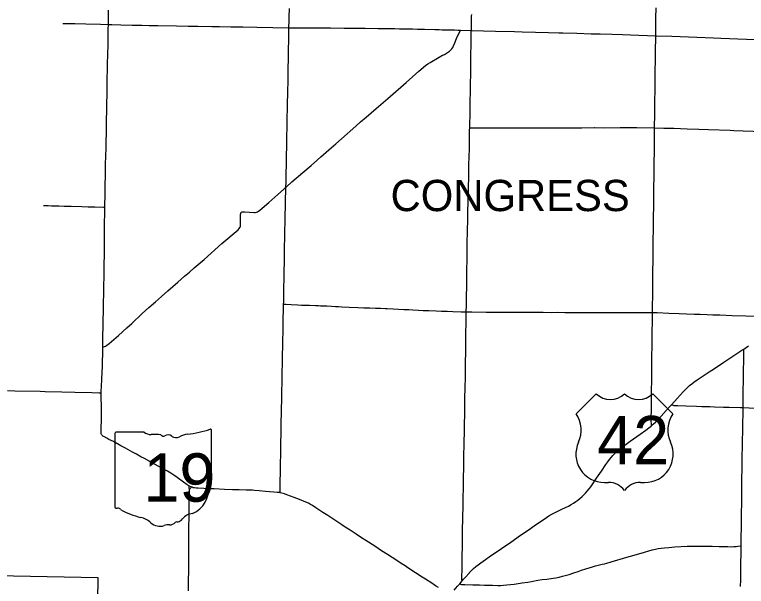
# Model space of a CAD drawing. Extents: x 9078 to 9739, y 4248 to 4966.
# Drawn here: x 9460 to 9565.4, y 4699.7 to 4782 of the extents above; entities that cross this region are included whole.
import ezdxf

# ---------------------------------------------------------------- set-up
doc = ezdxf.new("R2010")
doc.units = 0
for name, color, linetype in [('GM_X_County_Road', 7, 'Continuous'), ('GM_X_State_Route', 7, 'Continuous'), ('GM_X_State_Shield', 7, 'Continuous'), ('GM_X_Township', 7, 'Continuous'), ('GM_X_Township_Road', 7, 'Continuous'), ('GM_X_Township_Text', 7, 'Continuous'), ('GM_X_US_Route', 7, 'Continuous'), ('GM_X_US_Shield', 7, 'Continuous')]:
    doc.layers.add(name, color=color, linetype=linetype)

msp = doc.modelspace()

# ---------------------------------------------------------------- linework, layer by layer
at = {"layer": 'GM_X_County_Road'}
for points in [[(9499.49, 4780.1), (9499.49, 4780.17), (9499.5, 4780.99), (9499.51, 4781.64), (9499.54, 4782.87)], [(9525.74, 4779.71), (9525.75, 4779.86), (9525.76, 4780.44), (9525.77, 4781.34), (9525.79, 4781.75), (9525.82, 4781.99)], [(9499.05, 4757.13), (9499.07, 4757.84), (9499.07, 4758.17), (9499.09, 4758.82), (9499.09, 4759.4), (9499.11, 4760.13), (9499.13, 4760.95), (9499.14, 4761.53), (9499.14, 4761.85), (9499.15, 4762.18), (9499.16, 4762.51), (9499.17, 4763), (9499.19, 4763.66), (9499.2, 4764.56), (9499.23, 4765.62), (9499.25, 4766.35), (9499.25, 4766.74), (9499.25, 4766.98), (9499.25, 4767.3), (9499.25, 4767.54), (9499.26, 4768.03), (9499.26, 4768.61), (9499.28, 4769.18), (9499.29, 4769.67), (9499.3, 4770.17), (9499.32, 4770.9), (9499.34, 4771.47), (9499.35, 4771.88), (9499.37, 4772.79), (9499.38, 4773.44), (9499.39, 4773.85), (9499.39, 4774.59), (9499.4, 4775.25), (9499.42, 4776.31), (9499.44, 4777.05), (9499.45, 4778.2), (9499.49, 4780.1)], [(9499.05, 4757.13), (9499.12, 4757.2), (9499.92, 4757.9), (9501.47, 4759.24), (9502.66, 4760.25), (9503.59, 4761.06), (9504.08, 4761.49), (9505.24, 4762.52), (9506.23, 4763.39), (9507.03, 4764.1), (9509.11, 4765.94), (9509.79, 4766.54), (9510.59, 4767.24), (9512.02, 4768.48), (9513.7, 4769.92), (9516.36, 4772.23), (9518.21, 4773.85), (9519.16, 4774.64), (9519.49, 4774.89), (9519.83, 4775.11), (9521.11, 4775.85), (9521.61, 4776.12), (9521.89, 4776.26), (9522.31, 4776.51), (9522.58, 4776.7), (9522.76, 4776.87), (9522.92, 4777.06), (9523.06, 4777.26), (9523.18, 4777.47), (9523.37, 4777.92), (9523.61, 4778.53), (9523.8, 4778.98), (9524.02, 4779.43), (9524.14, 4779.64), (9524.2, 4779.75)], [(9499.49, 4780.1), (9499.74, 4780.1), (9500.31, 4780.09), (9501.95, 4780.09), (9504.33, 4780.07), (9505.47, 4780.06), (9507.44, 4780.04), (9508.59, 4780.04), (9510.48, 4780.02), (9512.28, 4780), (9513.18, 4779.99), (9514.74, 4779.96), (9515.39, 4779.95), (9515.64, 4779.94), (9516.13, 4779.94), (9517.28, 4779.92), (9518.01, 4779.9), (9518.42, 4779.89), (9518.99, 4779.88), (9520.47, 4779.84), (9521.12, 4779.82), (9521.53, 4779.81), (9523.01, 4779.78), (9523.33, 4779.77), (9523.82, 4779.76), (9524.2, 4779.75)], [(9524.2, 4779.75), (9525.74, 4779.71)], [(9525.51, 4765.67), (9525.53, 4766.09), (9525.56, 4767.65), (9525.58, 4768.47), (9525.58, 4769.12), (9525.59, 4769.61), (9525.62, 4770.76), (9525.63, 4771.66), (9525.66, 4773.8), (9525.69, 4775.02), (9525.69, 4776.01), (9525.71, 4777.81), (9525.73, 4778.88), (9525.74, 4779.71)], [(9525.74, 4779.71), (9525.87, 4779.7), (9527.51, 4779.67), (9529.23, 4779.61), (9531.94, 4779.53), (9533.08, 4779.49), (9534.97, 4779.44), (9536.85, 4779.39), (9538.33, 4779.35), (9538.9, 4779.35), (9540.95, 4779.29), (9543, 4779.22), (9544.31, 4779.2), (9546.03, 4779.15), (9547.5, 4779.11), (9548.65, 4779.08), (9552.31, 4778.95)], [(9552.14, 4765.7), (9552.14, 4766.16), (9552.15, 4767.23), (9552.15, 4767.72), (9552.17, 4768.62), (9552.18, 4769.36), (9552.18, 4770.02), (9552.2, 4770.67), (9552.21, 4771.66), (9552.22, 4772.56), (9552.24, 4774.12), (9552.25, 4775.1), (9552.26, 4775.76), (9552.28, 4776.83), (9552.31, 4778.71), (9552.31, 4778.8), (9552.31, 4778.95)], [(9552.31, 4778.95), (9552.42, 4778.95), (9554.63, 4778.87), (9560.61, 4778.63), (9561.68, 4778.59), (9565.37, 4778.46), (9567.09, 4778.4), (9567.99, 4778.38), (9569.38, 4778.33), (9571.27, 4778.27), (9573.89, 4778.19), (9576.92, 4778.09), (9577.91, 4778.06), (9578.2, 4778.04), (9578.33, 4778.02), (9578.46, 4777.99)], [(9525.02, 4739.17), (9525.02, 4739.28), (9525.03, 4740.02), (9525.05, 4741.17), (9525.08, 4743.13), (9525.09, 4744.2), (9525.12, 4745.51), (9525.13, 4746.41), (9525.15, 4748.05), (9525.15, 4748.55), (9525.16, 4749.53), (9525.18, 4750.35), (9525.2, 4751.33), (9525.22, 4751.99), (9525.23, 4752.65), (9525.26, 4753.79), (9525.28, 4754.86), (9525.3, 4755.68), (9525.33, 4756.58), (9525.35, 4757.32), (9525.37, 4758.38), (9525.39, 4759.53), (9525.41, 4760.35), (9525.47, 4762.65), (9525.48, 4763.55), (9525.5, 4765.11), (9525.5, 4765.35), (9525.51, 4765.67)], [(9551.83, 4739.08), (9551.83, 4739.66), (9551.86, 4741.88), (9551.88, 4744.01), (9551.89, 4745.08), (9551.91, 4746.47), (9551.92, 4747.21), (9551.92, 4748.03), (9551.93, 4748.77), (9551.95, 4749.75), (9551.96, 4750.82), (9551.98, 4751.97), (9552, 4753.12), (9552.02, 4754.1), (9552.03, 4755), (9552.03, 4755.66), (9552.04, 4756.48), (9552.05, 4757.38), (9552.07, 4758.37), (9552.07, 4759.44), (9552.09, 4760.99), (9552.1, 4761.98), (9552.1, 4762.39), (9552.11, 4763.04), (9552.13, 4764.6), (9552.14, 4765.59), (9552.14, 4765.7)], [(9492.62, 4753.5), (9492.67, 4753.54), (9492.74, 4753.57), (9492.82, 4753.58), (9493.07, 4753.58), (9493.81, 4753.52), (9494.47, 4753.5), (9494.63, 4753.51), (9494.79, 4753.54), (9494.95, 4753.59), (9495.09, 4753.67), (9495.29, 4753.81), (9496.59, 4754.95), (9497.89, 4756.09), (9498.68, 4756.8), (9499.05, 4757.13)], [(9498.71, 4740.29), (9498.73, 4740.63), (9498.75, 4741.53), (9498.75, 4741.94), (9498.76, 4742.76), (9498.79, 4743.91), (9498.81, 4745.22), (9498.82, 4746.13), (9498.84, 4746.7), (9498.85, 4747.44), (9498.85, 4748.26), (9498.85, 4748.58), (9498.89, 4749.73), (9498.91, 4750.88), (9498.93, 4752.03), (9498.94, 4752.6), (9498.95, 4753.01), (9498.96, 4753.42), (9498.97, 4753.99), (9498.98, 4754.56), (9498.99, 4754.89), (9499, 4755.63), (9499.03, 4756.37), (9499.05, 4756.94), (9499.05, 4757.13)], [(9472.68, 4734.1), (9472.93, 4734.2), (9473.09, 4734.26), (9473.23, 4734.34), (9473.61, 4734.65), (9474.92, 4735.78), (9476.14, 4736.87), (9476.87, 4737.53), (9478.37, 4738.94), (9479.33, 4739.83), (9480.26, 4740.64), (9481.12, 4741.4), (9482.05, 4742.21), (9483.47, 4743.45), (9484.46, 4744.32), (9485.14, 4744.91), (9485.82, 4745.5), (9487.26, 4746.73), (9489.84, 4749.01), (9492.15, 4751), (9492.32, 4751.17), (9492.41, 4751.31), (9492.44, 4751.38), (9492.49, 4751.54), (9492.52, 4751.78), (9492.52, 4752.77), (9492.52, 4753.18), (9492.54, 4753.35), (9492.56, 4753.43), (9492.61, 4753.49), (9492.62, 4753.5)], [(9498.22, 4713.14), (9498.22, 4713.36), (9498.22, 4713.85), (9498.24, 4714.51), (9498.24, 4715), (9498.25, 4715.82), (9498.27, 4716.48), (9498.28, 4717.21), (9498.29, 4717.79), (9498.3, 4718.28), (9498.3, 4718.61), (9498.31, 4719.26), (9498.31, 4719.67), (9498.32, 4720.25), (9498.33, 4720.82), (9498.34, 4721.23), (9498.34, 4721.56), (9498.36, 4722.38), (9498.38, 4723.44), (9498.4, 4724.43), (9498.41, 4725), (9498.43, 4725.74), (9498.44, 4725.98), (9498.44, 4726.14), (9498.46, 4726.63), (9498.46, 4726.95), (9498.47, 4727.36), (9498.47, 4727.77), (9498.48, 4728.18), (9498.49, 4728.59), (9498.5, 4729.08), (9498.5, 4729.41), (9498.52, 4729.98), (9498.53, 4730.89), (9498.54, 4731.38), (9498.55, 4732.2), (9498.56, 4732.69), (9498.57, 4733.34), (9498.59, 4733.84), (9498.6, 4734.57), (9498.61, 4734.9), (9498.62, 4735.39), (9498.63, 4736.05), (9498.66, 4737.52), (9498.67, 4738.51), (9498.68, 4739.16), (9498.68, 4739.41), (9498.7, 4739.98), (9498.71, 4740.22), (9498.71, 4740.29)], [(9524.43, 4700.45), (9524.4, 4700.67), (9524.4, 4701), (9524.42, 4702.15), (9524.44, 4702.97), (9524.45, 4703.38), (9524.45, 4703.87), (9524.45, 4704.52), (9524.46, 4704.85), (9524.47, 4705.51), (9524.47, 4706.57), (9524.48, 4707.23), (9524.49, 4707.8), (9524.49, 4708.13), (9524.51, 4709.03), (9524.53, 4709.93), (9524.55, 4710.92), (9524.55, 4711.41), (9524.56, 4712.23), (9524.58, 4712.8), (9524.6, 4713.45), (9524.61, 4713.95), (9524.62, 4714.77), (9524.63, 4715.42), (9524.65, 4716.65), (9524.68, 4718.37), (9524.72, 4720.18), (9524.75, 4722.15), (9524.78, 4723.38), (9524.79, 4724.03), (9524.83, 4726.33), (9524.88, 4728.7), (9524.89, 4729.36), (9524.91, 4730.59), (9524.93, 4732.15), (9524.94, 4733.13), (9524.95, 4734.12), (9524.96, 4735.35), (9524.97, 4736.25), (9524.99, 4737.4), (9525.01, 4738.54), (9525.02, 4739.17)], [(9525.02, 4739.17), (9525.83, 4739.17), (9527.88, 4739.15), (9528.78, 4739.15), (9530.01, 4739.14), (9531.57, 4739.13), (9533.78, 4739.12), (9535.01, 4739.12), (9536.08, 4739.12), (9537.23, 4739.11), (9538.21, 4739.12), (9539.2, 4739.11), (9540.92, 4739.11), (9543.14, 4739.1), (9544.53, 4739.1), (9545.43, 4739.09), (9547.16, 4739.1), (9549.21, 4739.09), (9550.27, 4739.09), (9551.59, 4739.09), (9551.83, 4739.08)], [(9551.69, 4722.78), (9551.67, 4723.09), (9551.66, 4723.42), (9551.66, 4723.91), (9551.67, 4725.14), (9551.68, 4726.04), (9551.7, 4727.85), (9551.72, 4729.32), (9551.73, 4730.23), (9551.73, 4731.21), (9551.75, 4732.36), (9551.77, 4734.66), (9551.81, 4736.54), (9551.82, 4737.53), (9551.82, 4738.18), (9551.83, 4739.08)], [(9551.83, 4739.08), (9552.49, 4739.07), (9554.21, 4739), (9555.69, 4738.95), (9556.75, 4738.91), (9557.9, 4738.87), (9558.72, 4738.84), (9559.7, 4738.8), (9560.52, 4738.77), (9561.51, 4738.74), (9563.31, 4738.67), (9565.28, 4738.61), (9566.59, 4738.57), (9567.98, 4738.52), (9569.54, 4738.48), (9570.12, 4738.46), (9571.43, 4738.42), (9571.84, 4738.4), (9572.01, 4738.4)], [(9458.96, 4727.86), (9460.03, 4727.83), (9463.64, 4727.76), (9464.38, 4727.74), (9466.76, 4727.67), (9468.65, 4727.62), (9471.11, 4727.56), (9472.17, 4727.54), (9472.46, 4727.53)]]:
    msp.add_lwpolyline(points, dxfattribs=at)
at = {"layer": 'GM_X_State_Route'}
msp.add_lwpolyline([(9521.02, 4699.48), (9520.61, 4699.76), (9520.06, 4700.12), (9519.16, 4700.68), (9518.68, 4700.99), (9517.72, 4701.62), (9516.62, 4702.35), (9516.21, 4702.61), (9515.66, 4702.97), (9515.04, 4703.37), (9514.35, 4703.81), (9513.66, 4704.26), (9512.83, 4704.79), (9511.87, 4705.43), (9510.56, 4706.26), (9509.94, 4706.66), (9509.18, 4707.16), (9508.29, 4707.74), (9507.6, 4708.18), (9507.12, 4708.5), (9505.82, 4709.36), (9505.06, 4709.85), (9504.38, 4710.31), (9503.36, 4710.99), (9502.87, 4711.3), (9502.59, 4711.47), (9502.29, 4711.62), (9501.92, 4711.79), (9501.01, 4712.17), (9500.24, 4712.46), (9499.17, 4712.86), (9498.86, 4712.97), (9498.46, 4713.08), (9498.22, 4713.14), (9498.06, 4713.17), (9497.81, 4713.19), (9497.32, 4713.22), (9496.67, 4713.26), (9496.09, 4713.31), (9495.2, 4713.4), (9494.54, 4713.47), (9494.22, 4713.5), (9493.8, 4713.51), (9493.31, 4713.52), (9492.33, 4713.55), (9491.35, 4713.58), (9490.2, 4713.61), (9488.72, 4713.68), (9487.82, 4713.72), (9487.25, 4713.74), (9486.43, 4713.78), (9486.1, 4713.8), (9485.86, 4713.84), (9485.7, 4713.87), (9485.54, 4713.92), (9485.47, 4713.95), (9485.39, 4713.97), (9485.17, 4714.08), (9485.11, 4714.12), (9485.03, 4714.16), (9484.83, 4714.3), (9484.3, 4714.68), (9483.37, 4715.35), (9482.89, 4715.68), (9482.47, 4715.94), (9481.98, 4716.23), (9481.26, 4716.64), (9480.11, 4717.26), (9478.67, 4718.05), (9478.16, 4718.32), (9477.52, 4718.68), (9476.95, 4719), (9475.93, 4719.54), (9475.29, 4719.9), (9474.21, 4720.5), (9473.55, 4720.83), (9473.27, 4720.99), (9472.83, 4721.22), (9472.69, 4721.3), (9472.62, 4721.35), (9472.57, 4721.4), (9472.52, 4721.46), (9472.48, 4721.53), (9472.45, 4721.6), (9472.44, 4721.68), (9472.43, 4721.76), (9472.43, 4722), (9472.45, 4722.66), (9472.47, 4723.4), (9472.49, 4724.38), (9472.49, 4724.96), (9472.48, 4725.78), (9472.46, 4726.6), (9472.45, 4727.17), (9472.46, 4727.53), (9472.46, 4727.74), (9472.49, 4728.48), (9472.56, 4729.46), (9472.61, 4730.53), (9472.64, 4731.26), (9472.65, 4731.92), (9472.67, 4733.23), (9472.68, 4734.1), (9472.68, 4734.14), (9472.69, 4734.96), (9472.7, 4735.94), (9472.72, 4736.84), (9472.75, 4738.32), (9472.77, 4738.97), (9472.8, 4740.53), (9472.82, 4741.76), (9472.85, 4743.24), (9472.86, 4743.98), (9472.87, 4744.8), (9472.87, 4745.46), (9472.88, 4746.28), (9472.9, 4747.1), (9472.9, 4747.92), (9472.9, 4749.23), (9472.9, 4749.72), (9472.91, 4750.38), (9472.91, 4750.71), (9472.92, 4751.12), (9472.94, 4752.02), (9472.94, 4752.43), (9472.95, 4752.92), (9472.95, 4753.49), (9472.96, 4754.15), (9472.97, 4754.27), (9472.97, 4754.8), (9473, 4755.71), (9473.03, 4757.59), (9473.05, 4758.66), (9473.07, 4759.56), (9473.09, 4760.71), (9473.1, 4761.37), (9473.15, 4763.01), (9473.18, 4763.99), (9473.19, 4764.64), (9473.23, 4766.78), (9473.24, 4768.17), (9473.27, 4769.16), (9473.29, 4770.55), (9473.31, 4771.21), (9473.32, 4771.95), (9473.32, 4772.52), (9473.33, 4773.18), (9473.34, 4773.67), (9473.35, 4774.12), (9473.35, 4774.32), (9473.36, 4774.9), (9473.37, 4775.22), (9473.4, 4775.88), (9473.42, 4776.7), (9473.43, 4777.19), (9473.44, 4777.69), (9473.44, 4778.18), (9473.44, 4778.34), (9473.44, 4778.51), (9473.44, 4778.91), (9473.44, 4779.08), (9473.45, 4779.32), (9473.45, 4779.57), (9473.46, 4779.89), (9473.48, 4780.55), (9473.48, 4780.57), (9473.49, 4781.04), (9473.5, 4781.61), (9473.52, 4782.6)], dxfattribs=at)
at = {"layer": 'GM_X_State_Shield'}
for p, q in [((9474.41, 4721.67), (9474.41, 4711.11)), ((9478.62, 4721.85), (9474.55, 4721.85)), ((9488.33, 4716.59), (9488.33, 4722.12)), ((9488.33, 4716.59), (9488.33, 4716.59))]:
    msp.add_line(p, q, dxfattribs=at)
for centre, radius, start, end in [((9474.57, 4721.69), 0.161, 98.1301, 188.1301), ((9479.59, 4723.08), 1.56, 231.6195, 271.1119), ((9485.25, 4718.63), 2.97, 97.3462, 120.7689), ((9483.37, 4736.26), 14.76, 275.8445, 288.9065), ((9488.18, 4722.14), 0.155, 351.8621, 97.738), ((9480.11, 4715.92), 5.62, 80.4867, 94.9883), ((9481.39, 4721.75), 0.451, 219.7921, 297.1024), ((9482.05, 4720.53), 0.938, 54.4667, 119.1411), ((9483.26, 4722.2), 1.13, 233.8562, 294.8282), ((9488.29, 4716.18), 0.24, 107.944, 210.337), ((9488.17, 4716.57), 0.166, 289.6038, 7.7341), ((9486.77, 4715.48), 1.44, 340.033, 23.6496), ((9488.89, 4714.27), 1.05, 136.8065, 186.9296), ((9484.2, 4713.57), 3.69, 292.3089, 8.9858), ((9474.57, 4711.08), 0.163, 171.9584, 258.3066), ((9474.59, 4712.16), 1.24, 267.339, 280.6039), ((9474.85, 4710.5), 0.448, 29.7484, 93.2717), ((9480.5, 4719.99), 10.66, 240.4129, 257.1985), ((9485.76, 4708.14), 2.02, 94.4031, 142.5768), ((9477.32, 4706.36), 3.34, 47.1842, 75.836), ((9483.33, 4708.63), 0.318, 65.7517, 132.6484), ((9483.19, 4710.08), 1.19, 282.8732, 323.2771), ((9480.93, 4710.44), 2.12, 230.7004, 286.2918), ((9482.15, 4706.79), 1.74, 85.6951, 111.2099), ((9482.31, 4709.65), 1.13, 268.777, 315.5493)]:
    msp.add_arc(centre, radius, start, end, dxfattribs=at)
at = {"layer": 'GM_X_Township'}
msp.add_lwpolyline([(9471.81, 4687.76), (9472, 4700.88), (9440.23, 4701.51)], dxfattribs=at)
at = {"layer": 'GM_X_Township_Road'}
for points in [[(9552.31, 4778.95), (9552.32, 4779.73), (9552.33, 4781.46), (9552.34, 4782.94)], [(9466.93, 4780.7), (9467.67, 4780.69)], [(9467.67, 4780.69), (9468.66, 4780.68), (9470.22, 4780.65), (9472.36, 4780.6), (9473.48, 4780.57)], [(9473.48, 4780.57), (9473.63, 4780.57), (9473.96, 4780.57), (9475.27, 4780.53), (9476.91, 4780.47), (9478.31, 4780.44), (9479.37, 4780.42), (9480.6, 4780.41), (9483.31, 4780.37), (9484.95, 4780.33), (9486.35, 4780.31), (9488.4, 4780.29), (9489.47, 4780.27), (9491.11, 4780.24), (9492.83, 4780.21), (9494.88, 4780.19), (9497.18, 4780.14), (9499.49, 4780.1)], [(9525.51, 4765.67), (9525.69, 4765.67), (9527.01, 4765.67), (9528.57, 4765.67), (9530.53, 4765.68), (9531.93, 4765.69), (9533.24, 4765.69), (9534.8, 4765.68), (9536.76, 4765.68), (9538.4, 4765.68), (9539.96, 4765.68), (9540.78, 4765.68), (9541.68, 4765.69), (9543.42, 4765.71)], [(9543.42, 4765.71), (9543.49, 4765.71), (9544.72, 4765.69), (9547.18, 4765.71), (9549.56, 4765.71), (9552.1, 4765.7), (9552.14, 4765.7)], [(9552.14, 4765.7), (9553.49, 4765.65), (9554.89, 4765.61), (9556.85, 4765.55), (9558.49, 4765.49), (9559.89, 4765.45), (9563, 4765.33), (9563.57, 4765.3), (9564.89, 4765.26), (9567.75, 4765.15), (9569.56, 4765.08), (9571.77, 4765.01), (9573.82, 4764.94), (9575.05, 4764.91), (9577.1, 4764.86), (9578.16, 4764.84), (9578.35, 4764.83)], [(9464.16, 4754.49), (9464.8, 4754.48), (9465.28, 4754.47), (9465.34, 4754.47)], [(9465.34, 4754.47), (9465.57, 4754.46), (9465.82, 4754.45), (9465.9, 4754.45), (9466.06, 4754.44), (9466.33, 4754.43), (9467.13, 4754.41), (9468.11, 4754.38), (9469.67, 4754.36), (9470.57, 4754.33), (9471.55, 4754.3), (9472.78, 4754.28), (9472.97, 4754.27)], [(9498.71, 4740.29), (9498.9, 4740.27), (9499.06, 4740.27), (9499.8, 4740.23), (9500.78, 4740.18), (9501.27, 4740.16), (9501.44, 4740.16), (9501.84, 4740.14), (9502.42, 4740.13), (9503.32, 4740.1), (9503.73, 4740.08), (9504.05, 4740.07), (9504.96, 4740.04), (9505.61, 4740), (9506.19, 4739.97), (9506.6, 4739.95), (9507.09, 4739.93), (9508.15, 4739.88), (9509.38, 4739.83), (9510.29, 4739.78), (9511.11, 4739.75), (9511.93, 4739.73), (9512.66, 4739.7), (9513.32, 4739.67), (9513.65, 4739.66), (9514.47, 4739.61), (9516.02, 4739.54), (9516.76, 4739.5), (9517.33, 4739.47), (9518.15, 4739.43), (9518.81, 4739.4), (9519.63, 4739.37), (9520.7, 4739.33), (9521.43, 4739.3), (9522.25, 4739.27), (9523.07, 4739.23), (9524.3, 4739.19), (9524.8, 4739.18), (9525.02, 4739.17)], [(9564.87, 4725.39), (9564.87, 4725.75), (9564.91, 4727.64), (9564.93, 4729.44), (9564.96, 4730.59), (9564.99, 4732.31), (9565, 4733.29), (9564.99, 4733.54), (9564.97, 4733.82)], [(9554.58, 4725.81), (9554.8, 4725.73), (9554.91, 4725.71), (9555.48, 4725.68), (9556.63, 4725.65), (9558.19, 4725.6), (9558.93, 4725.58), (9560.08, 4725.55), (9560.74, 4725.52), (9562.05, 4725.48), (9562.87, 4725.45), (9564.51, 4725.4), (9564.87, 4725.39)], [(9564.6, 4705.5), (9564.61, 4706.17), (9564.62, 4706.74), (9564.65, 4708.14), (9564.66, 4708.79), (9564.66, 4709.37), (9564.67, 4710.35), (9564.68, 4711.5), (9564.7, 4712.89), (9564.71, 4714.28), (9564.72, 4715.35), (9564.73, 4716.41), (9564.75, 4717.64), (9564.77, 4718.54), (9564.79, 4719.61), (9564.8, 4720.26), (9564.8, 4720.84), (9564.82, 4721.82), (9564.85, 4723.46), (9564.87, 4724.2), (9564.87, 4725.18), (9564.87, 4725.39)], [(9564.87, 4725.39), (9565.74, 4725.36), (9567.55, 4725.29), (9568.29, 4725.27), (9568.86, 4725.26), (9570.1, 4725.19), (9571, 4725.16), (9572.15, 4725.11), (9572.72, 4725.1), (9574.2, 4725.05), (9575.1, 4725.01), (9576.33, 4724.97), (9576.91, 4724.93), (9577.4, 4724.89), (9577.64, 4724.86), (9577.69, 4724.86)], [(9485, 4699.02), (9485.03, 4700.49), (9485.05, 4701.89), (9485.05, 4702.46), (9485.06, 4703.2), (9485.07, 4703.77), (9485.08, 4705.17), (9485.09, 4705.74), (9485.09, 4706.64), (9485.09, 4707.38), (9485.09, 4708.28), (9485.11, 4709.51), (9485.11, 4710.25), (9485.12, 4710.9), (9485.11, 4711.4), (9485.12, 4712.22), (9485.14, 4713.28), (9485.14, 4713.58)], [(9485.14, 4713.58), (9485.14, 4713.61), (9485.12, 4713.86), (9485.11, 4714.12)], [(9485.14, 4713.58), (9485.19, 4713.65), (9485.28, 4713.76), (9485.32, 4713.81), (9485.47, 4713.95)], [(9524.07, 4700.04), (9524.2, 4699.98), (9524.32, 4699.95), (9524.79, 4699.93), (9525.94, 4699.89), (9526.92, 4699.87), (9527.66, 4699.85), (9528.4, 4699.83), (9528.81, 4699.82), (9529.55, 4699.8), (9529.96, 4699.8), (9530.37, 4699.81), (9530.86, 4699.86), (9531.91, 4700), (9533.05, 4700.17), (9533.86, 4700.28), (9534.43, 4700.38), (9535.32, 4700.53), (9535.97, 4700.63), (9536.62, 4700.72), (9537.51, 4700.84), (9537.92, 4700.9), (9538.4, 4701), (9538.88, 4701.11), (9539.43, 4701.26), (9539.83, 4701.38), (9540.53, 4701.61), (9541.15, 4701.82), (9541.61, 4701.99), (9542.23, 4702.2), (9542.7, 4702.35), (9543.18, 4702.49), (9543.65, 4702.62), (9544.21, 4702.75), (9544.61, 4702.84), (9544.93, 4702.92), (9545.24, 4703), (9545.88, 4703.18), (9548.16, 4703.85), (9549.18, 4704.16), (9550.68, 4704.59), (9551.31, 4704.78), (9551.78, 4704.9), (9552.26, 4705.02), (9552.66, 4705.09), (9553.07, 4705.16), (9553.56, 4705.22), (9554.21, 4705.28), (9555.03, 4705.34), (9556.83, 4705.44), (9557.65, 4705.46), (9558.31, 4705.47), (9559.05, 4705.46), (9559.62, 4705.45), (9560.44, 4705.43), (9561.43, 4705.41), (9562.66, 4705.38), (9563.23, 4705.37), (9563.56, 4705.38), (9563.89, 4705.4), (9564.13, 4705.43), (9564.6, 4705.5)], [(9564.53, 4699.65), (9564.56, 4700.61), (9564.56, 4700.94), (9564.56, 4701.59), (9564.56, 4702.16), (9564.56, 4702.66), (9564.56, 4703.15), (9564.57, 4703.48), (9564.58, 4703.9), (9564.58, 4704.46), (9564.59, 4705.19), (9564.6, 4705.5)]]:
    msp.add_lwpolyline(points, dxfattribs=at)
at = {"layer": 'GM_X_US_Route'}
for points in [[(9525.49, 4701.63), (9525.5, 4701.65), (9525.79, 4701.95), (9526.08, 4702.23), (9526.39, 4702.5), (9526.71, 4702.76), (9527.1, 4703.06), (9527.77, 4703.53), (9528.31, 4703.9), (9530.07, 4705.11), (9531.42, 4706.04), (9532.84, 4707.01), (9533.92, 4707.76), (9534.79, 4708.37), (9536.55, 4709.58), (9536.89, 4709.8), (9537.32, 4710.05), (9537.61, 4710.2), (9538.2, 4710.49), (9538.79, 4710.76), (9539.31, 4711), (9539.75, 4711.23), (9540.11, 4711.43), (9540.46, 4711.65), (9540.8, 4711.88), (9541.07, 4712.07), (9541.39, 4712.33), (9541.7, 4712.6), (9541.94, 4712.83), (9542.17, 4713.06), (9542.44, 4713.36), (9542.71, 4713.68), (9542.96, 4714), (9543.15, 4714.27), (9543.78, 4715.23), (9544.47, 4716.26), (9545.11, 4717.21), (9545.4, 4717.6), (9545.65, 4717.92), (9545.92, 4718.24), (9546.13, 4718.48), (9546.42, 4718.78), (9546.71, 4719.07), (9547.01, 4719.34), (9547.32, 4719.6), (9547.65, 4719.85), (9548.64, 4720.57), (9550.06, 4721.56), (9550.86, 4722.13), (9551.32, 4722.48), (9551.64, 4722.74), (9551.69, 4722.78), (9551.94, 4723.01), (9552.3, 4723.35), (9552.71, 4723.76), (9553.1, 4724.17), (9553.82, 4724.97), (9554.42, 4725.64), (9554.58, 4725.81), (9555.41, 4726.73), (9556.24, 4727.65), (9556.58, 4728), (9556.87, 4728.29), (9557.17, 4728.56), (9557.49, 4728.82), (9557.81, 4729.07), (9558.28, 4729.41), (9558.82, 4729.78), (9559.99, 4730.54), (9560.74, 4731.04), (9561.97, 4731.86), (9563.41, 4732.8), (9564.72, 4733.65), (9564.97, 4733.82), (9565.68, 4734.28)], [(9524.07, 4700.04), (9524.43, 4700.45), (9524.63, 4700.68), (9524.85, 4700.92), (9525.49, 4701.63)], [(9523.28, 4699.13), (9523.76, 4699.69), (9524.07, 4700.04)]]:
    msp.add_lwpolyline(points, dxfattribs=at)
at = {"layer": 'GM_X_US_Shield'}
for p, q in [((9543.74, 4727.4), (9540.84, 4724.49)), ((9554.76, 4724.49), (9551.86, 4727.4)), ((9544.9, 4714.63), (9545.48, 4714.63)), ((9550.12, 4714.63), (9550.7, 4714.63))]:
    msp.add_line(p, q, dxfattribs=at)
for centre, radius, start, end in [((9545.77, 4729.47), 2.9, 225.573, 314.427), ((9549.83, 4729.47), 2.9, 225.573, 314.427), ((9537.52, 4722.17), 4.06, 334.5471, 35.0009), ((9558.09, 4722.17), 4.06, 144.9991, 205.4529), ((9544.86, 4718.69), 4.06, 154.8319, 270.6383), ((9550.75, 4718.69), 4.06, 269.3617, 25.1681), ((9545.48, 4711.73), 2.9, 36.8699, 90), ((9550.12, 4711.73), 2.9, 90, 143.1301)]:
    msp.add_arc(centre, radius, start, end, dxfattribs=at)

# ---------------------------------------------------------------- texts
at = {"layer": 'GM_X_State_Shield'}
msp.add_text('19', height=6.961, dxfattribs=at).set_placement((9478.53, 4711.85))
at = {"layer": 'GM_X_Township_Text'}
msp.add_text('CONGRESS', height=4.5, rotation=0, dxfattribs=at).set_placement((9514.12, 4753.69))
at = {"layer": 'GM_X_US_Shield'}
msp.add_text('42', height=6.961, dxfattribs=at).set_placement((9543.88, 4717.24))

doc.saveas('drawing.dxf')
